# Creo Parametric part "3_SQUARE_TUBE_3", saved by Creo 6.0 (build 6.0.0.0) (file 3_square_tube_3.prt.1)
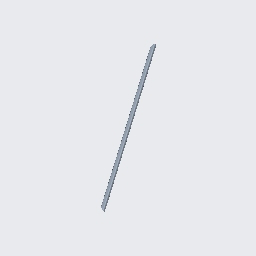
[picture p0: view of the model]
Units: Custom; MM, KILOGRAM, SECS
Materials in the file: STEEL

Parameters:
  BUW_NAME = "SQUARE TUBE"
  BUW_TYPE = "DIN EN 10219"
  BUW_SIZE = "25x25x3.0"
  BUW_LENGTH_STR = "1235"
  PTC_MATERIAL_NAME = "STEEL"
  BUW_PROFIL_TYPE = "square_tube"
  BUW_PROFILE_PATH = "parts//profiles/steel_beams_mm/"
  BUW_PROFILE_NAME_LANG = "SQUARE TUBE"
  BUW_TAB_SEL_INFO = "-2 TYPE DIN_EN_10219-1997 SIZE_DINEN_10219 25x25x3.0"
  NAMING = "SQUARE TUBE"
  DESIGNATION = "DIN EN 10219 25x25x3.0 x 1235"
  PROFIL_RASTER_POS = "X_0"
  BUW_OBJECT_ROLE = "PROFIL_SYSTEM_BORE_END_POINTS"
  PRO_UNIT_SYS = "Custom"

Other parameters: BUW_LENGTH, LENGTH, BUW_LENGTH_Z_MIN_PARAM, D8, D93, D94, d26, d8, d93, d94, d98, D98, SHEAR_MODULUS, THERM_EXPANSION_REF_TEMPERATURE, STRUCTURAL_DAMPING_COEFFICIENT, STRESS_LIMIT_FOR_TENSION, STRESS_LIMIT_FOR_COMPRESSION, STRESS_LIMIT_FOR_SHEAR, EMISSIVITY

Created from: SQUARE_TUBE.PRT

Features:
  1. datum plane "YZ"
  2. datum plane "XZ"
  3. datum plane "XY"
  4. coordinate system
  5. coordinate system
  6. coordinate system
  7. coordinate system
  8. datum plane "DTM3"
  9. datum plane "DTM4"
  10. datum plane "DTM5"
  11. protrusion
  12. round
  13. round
  14. datum axis
  15. datum point "PNT0"
  16. datum point

Other named items: PROFIL_CUT_QUILT, PROFILE_LENGTH_DIM, CONTACT_SURF_3, CONTACT_SURF_2, CONTACT_SURF_1, CONTACT_SURF_0, E, START_SURFACE, END_SURFACE, SIDE_SURF_3, SIDE_SURF_0, SIDE_SURF_1, SIDE_SURF_2, EDGE_7_S, EDGE_7_E, EDGE_1_S, EDGE_1_E, EDGE_3_S, EDGE_3_E, EDGE_5_S, EDGE_5_E, EDGE_6_S, EDGE_4_S, EDGE_2_S, EDGE_0_S, EDGE_6_E, EDGE_4_E, EDGE_2_E, EDGE_0_E, CS0, CS_S, CS_E, CS3

Named dimensions: X_ROT_S, Y_ROT_S, Z_OFF_S, X_ROT_E, Y_ROT_E, Z_OFF_E, PC_L, BUW_LENGTH_Z_MIN, BUW_LENGTH_DIM

Layers: 00_PROFIL_DATUM, 00_PROFIL_DRW_HIDE, 00_PROFIL_END_CSYS, 00_PROFIL_GEOMETRY, 00_PROFIL_QUILT, 00_PROFIL_SIZE_NOTE

Surfaces: 16 plane, 12 cylinder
